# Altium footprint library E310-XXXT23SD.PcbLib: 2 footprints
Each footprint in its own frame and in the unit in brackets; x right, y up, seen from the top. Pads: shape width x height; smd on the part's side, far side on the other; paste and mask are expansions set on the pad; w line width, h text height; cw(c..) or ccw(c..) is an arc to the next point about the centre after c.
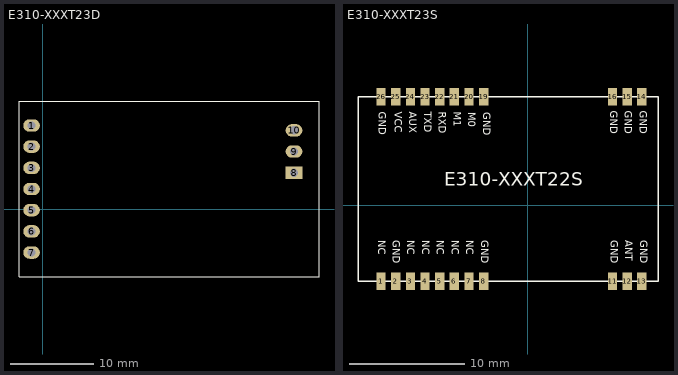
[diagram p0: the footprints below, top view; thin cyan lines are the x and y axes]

## E310-XXXT23D [mm]
pads (10):
  oval 2x1.5 hole 0.95: 1(-1.36,10.068) 2(-1.36,7.528) 3(-1.36,4.988) 4(-1.36,2.448) 5(-1.36,-0.092) 6(-1.36,-2.632) 7(-1.36,-5.172)
  rect 2x1.5 hole 1: 8(30.13,4.408)
  oval 2x1.5 hole 1: 9(30.13,6.948) 10(30.13,9.488)
Top Overlay:
  lines w0.1: -2.87,-8.052 33.13,-8.052 33.13,12.948 -2.87,12.948 -2.87,-8.052

## E310-XXXT23S [mm]
pads (22):
  rect 0.8x1.5 smd: 1(-12.694,-6.602) 2(-11.424,-6.602) 3(-10.154,-6.602) 4(-8.884,-6.602) 5(-7.614,-6.602) 6(-6.344,-6.602) 7(-5.074,-6.602) 8(-3.804,-6.602) 11(7.366,-6.602) 12(8.636,-6.602) 13(9.906,-6.602) 14(9.906,9.398) 15(8.636,9.398) 16(7.366,9.398) 19(-3.804,9.398) 20(-5.074,9.398) 21(-6.344,9.398) 22(-7.614,9.398) 23(-8.884,9.398) 24(-10.154,9.398) 25(-11.424,9.398) 26(-12.694,9.398)
Top Overlay:
  lines w0.127: -14.694,-6.602 11.306,-6.602 11.306,9.398 -14.694,9.398 -14.694,-6.602
  text "GND" at 8.219,8.174 h1.1
  text "GND" at 6.94,8.174 h1.1
  text "GND" at 6.99,-3.043 h1.1
  text "ANT" at 8.269,-3.043 h1.1
  text "GND" at 9.548,-3.043 h1.1
  text "GND" at -4.232,-3.043 h1.1
  text "NC" at -5.511,-3.043 h1.1
  text "NC" at -6.79,-3.043 h1.1
  text "NC" at -8.068,-3.043 h1.1
  text "NC" at -9.347,-3.043 h1.1
  text "NC" at -10.626,-3.043 h1.1
  text "GND" at -11.905,-3.043 h1.1
  text "NC" at -13.154,-3.043 h1.1
  text "GND" at -4.064,8.047 h1.1
  text "GND" at -13.104,8.097 h1.1
  text "VCC" at -11.745,8.097 h1.1
  text "AUX" at -10.466,8.097 h1.1
  text "TXD" at -9.187,8.097 h1.1
  text "RXD" at -7.908,8.097 h1.1
  text "M1" at -6.63,8.097 h1.1
  text "M0" at -5.351,8.047 h1.1
  text "E310-XXXT22S" at -7.201,1.272 h2
  text "GND" at 9.498,8.174 h1.1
